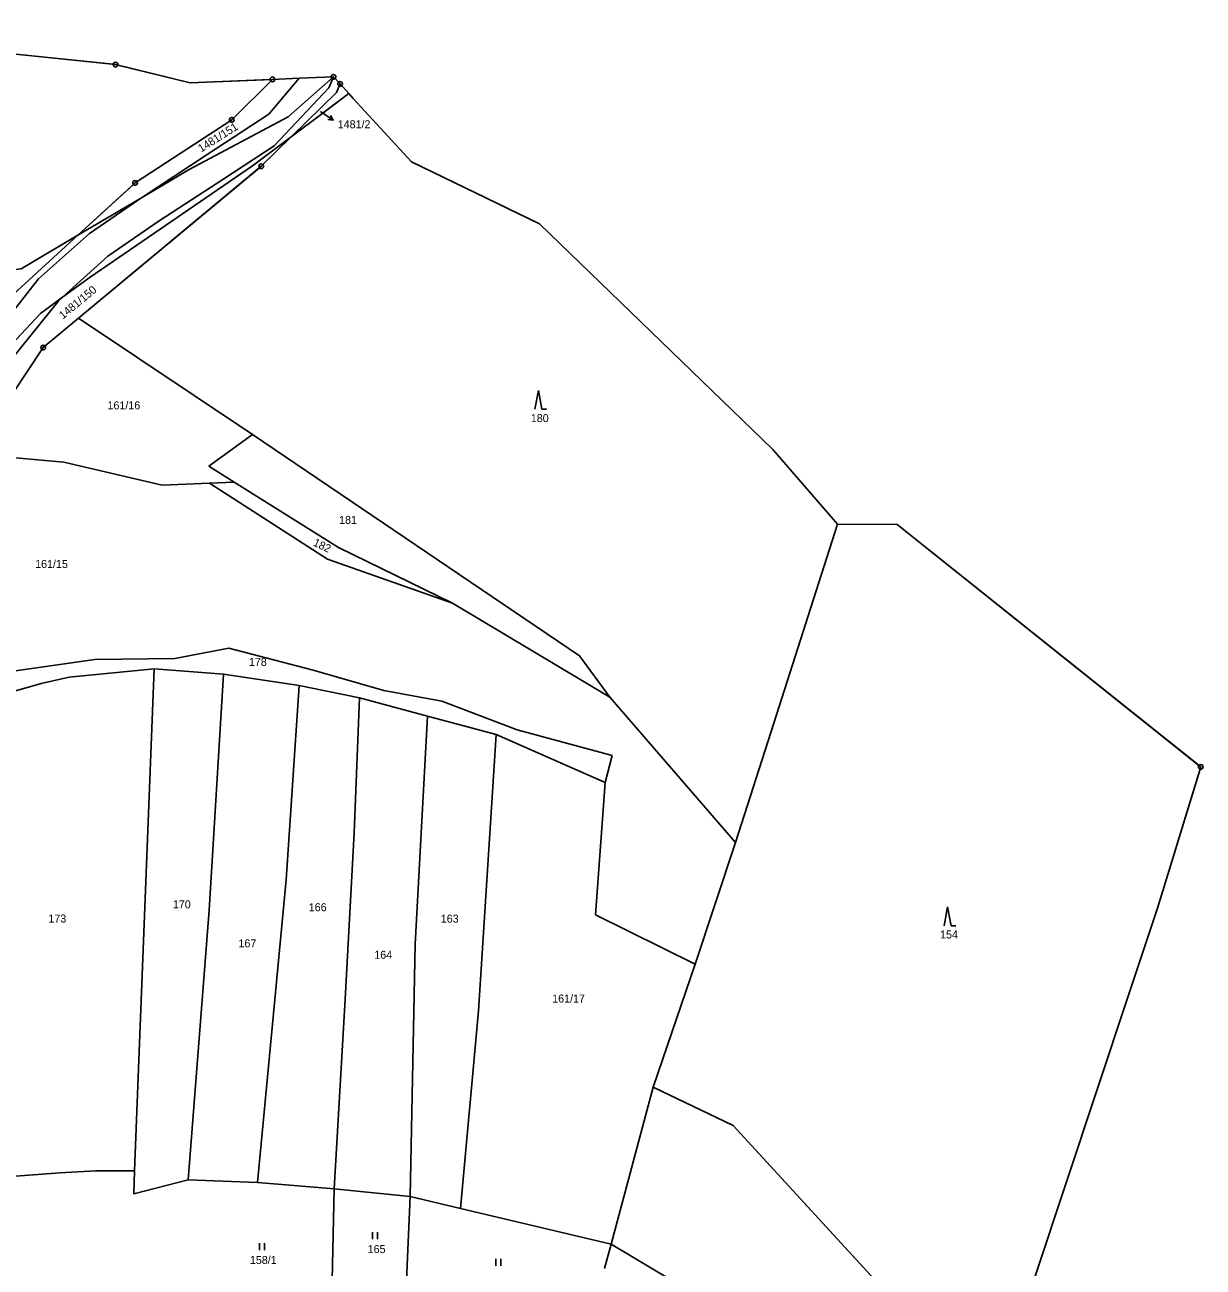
# Model space of a CAD drawing. Extents: x -760642 to -757221, y -1092371 to -1088855.
# Drawn here: x -758346.2 to -758095.9, y -1089414.4 to -1089150.5 of the extents above; entities that cross this region are included whole.
import ezdxf

# ---------------------------------------------------------------- set-up
doc = ezdxf.new("R2010")
doc.units = 0
for name, color, linetype in [('Vrstva 1', 7, 'Continuous'), ('Vrstva 13', 7, 'Continuous'), ('Vrstva 16', 7, 'Continuous'), ('Vrstva 18', 7, 'Continuous'), ('Vrstva 24', 7, 'Continuous'), ('Vrstva 25', 7, 'Continuous'), ('Vrstva 30', 7, 'Continuous'), ('Vrstva 4', 7, 'Continuous')]:
    doc.layers.add(name, color=color, linetype=linetype)

msp = doc.modelspace()

# ---------------------------------------------------------------- linework, layer by layer
at = {"layer": 'Vrstva 1'}
for p, q in [((-758302.25, -1089170.72), (-758293.6, -1089162.1)), ((-758280.62, -1089161.57), (-758290.27, -1089170.05)), ((-758280.03, -1089164.88), (-758279.25, -1089163.07)), ((-758280.03, -1089164.88), (-758289.61, -1089174.3)), ((-758289.61, -1089174.3), (-758277.37, -1089165.11)), ((-758302.25, -1089170.72), (-758322.78, -1089184.1)), ((-758290.27, -1089170.05), (-758311.27, -1089181.26)), ((-758297.83, -1089180.46), (-758289.61, -1089174.3)), ((-758289.61, -1089174.3), (-758296, -1089180.57)), ((-758296, -1089180.57), (-758334.79, -1089212.82)), ((-758297.83, -1089180.46), (-758332.36, -1089204.09)), ((-758311.27, -1089181.26), (-758321.42, -1089187.24)), ((-758322.78, -1089184.1), (-758334.92, -1089195.2)), ((-758321.42, -1089187.24), (-758334.92, -1089195.2)), ((-758334.92, -1089195.2), (-758353.94, -1089212.58)), ((-758334.92, -1089195.2), (-758347.02, -1089202.33)), ((-758332.36, -1089204.09), (-758338.21, -1089208.39)), ((-758338.21, -1089208.39), (-758342.91, -1089211.84)), ((-758342.91, -1089211.84), (-758351.13, -1089220.61)), ((-758334.79, -1089212.82), (-758342.31, -1089219.07)), ((-758297.86, -1089237.52), (-758334.79, -1089212.82)), ((-758342.31, -1089219.07), (-758357.37, -1089241.64)), ((-758297.86, -1089237.52), (-758307.12, -1089244.28)), ((-758228.38, -1089284.52), (-758297.86, -1089237.52)), ((-758357.37, -1089241.64), (-758337.94, -1089243.41)), ((-758337.94, -1089243.41), (-758317.03, -1089248.27)), ((-758307.12, -1089244.28), (-758301.74, -1089247.65)), ((-758306.95, -1089247.86), (-758301.74, -1089247.65)), ((-758301.74, -1089247.65), (-758279.56, -1089261.51)), ((-758317.03, -1089248.27), (-758306.95, -1089247.86)), ((-758281.94, -1089264.02), (-758306.95, -1089247.86)), ((-758173.59, -1089256.56), (-758187.13, -1089298.82)), ((-758279.56, -1089261.51), (-758255.35, -1089273.35)), ((-758255.35, -1089273.35), (-758281.94, -1089264.02)), ((-758255.35, -1089273.35), (-758221.9, -1089293.3)), ((-758314.36, -1089285.09), (-758302.84, -1089282.89)), ((-758302.84, -1089282.89), (-758284.96, -1089287.55)), ((-758221.9, -1089293.3), (-758228.38, -1089284.52)), ((-758355.84, -1089288.82), (-758331.34, -1089285.31)), ((-758331.34, -1089285.31), (-758314.36, -1089285.09)), ((-758342.75, -1089290.44), (-758336.79, -1089289.05)), ((-758336.79, -1089289.05), (-758318.74, -1089287.31)), ((-758322.92, -1089393.9), (-758318.74, -1089287.31)), ((-758318.74, -1089287.31), (-758303.99, -1089288.45)), ((-758303.99, -1089288.45), (-758307.04, -1089338.52)), ((-758303.99, -1089288.45), (-758287.95, -1089290.83)), ((-758284.96, -1089287.55), (-758269.97, -1089291.89)), ((-758350.4, -1089292.58), (-758342.75, -1089290.44)), ((-758287.95, -1089290.83), (-758290.7, -1089332.12)), ((-758287.95, -1089290.83), (-758275.12, -1089293.45)), ((-758269.97, -1089291.89), (-758257.63, -1089294.18)), ((-758275.12, -1089293.45), (-758276.26, -1089322.15)), ((-758275.12, -1089293.45), (-758260.65, -1089297.35)), ((-758257.63, -1089294.18), (-758241.61, -1089300.28)), ((-758195.26, -1089324.21), (-758221.9, -1089293.3)), ((-758263.32, -1089345.75), (-758260.65, -1089297.35)), ((-758260.65, -1089297.35), (-758246.05, -1089301.28)), ((-758241.61, -1089300.28), (-758221.45, -1089305.74)), ((-758187.13, -1089298.82), (-758195.26, -1089324.21)), ((-758249.83, -1089359.96), (-758246.05, -1089301.28)), ((-758246.05, -1089301.28), (-758222.9, -1089311.46)), ((-758222.9, -1089311.46), (-758221.45, -1089305.74)), ((-758222.9, -1089311.46), (-758225.01, -1089339.52)), ((-758276.26, -1089322.15), (-758278.16, -1089357.46)), ((-758195.26, -1089324.21), (-758203.78, -1089350.04)), ((-758290.7, -1089332.12), (-758296.79, -1089396.4)), ((-758307.04, -1089338.52), (-758311.53, -1089395.83)), ((-758225.01, -1089339.52), (-758203.78, -1089350.04)), ((-758264.35, -1089399.34), (-758263.32, -1089345.75)), ((-758203.78, -1089350.04), (-758212.75, -1089376.15)), ((-758278.16, -1089357.46), (-758280.49, -1089397.73)), ((-758253.63, -1089401.91), (-758249.83, -1089359.96)), ((-758212.75, -1089376.15), (-758221.64, -1089409.49)), ((-758212.75, -1089376.15), (-758195.73, -1089384.3)), ((-758195.73, -1089384.3), (-758162.53, -1089420.44)), ((-758350.93, -1089395.23), (-758338.76, -1089394.33)), ((-758338.76, -1089394.33), (-758331.15, -1089393.9)), ((-758331.15, -1089393.9), (-758322.92, -1089393.9)), ((-758323.09, -1089398.79), (-758322.92, -1089393.9)), ((-758311.53, -1089395.83), (-758323.09, -1089398.79)), ((-758311.53, -1089395.83), (-758296.79, -1089396.4)), ((-758296.79, -1089396.4), (-758280.49, -1089397.73)), ((-758280.49, -1089397.73), (-758281.08, -1089425.85)), ((-758280.49, -1089397.73), (-758264.35, -1089399.34)), ((-758265.53, -1089426.1), (-758264.35, -1089399.34)), ((-758264.35, -1089399.34), (-758253.63, -1089401.91)), ((-758253.63, -1089401.91), (-758221.64, -1089409.49)), ((-758221.64, -1089409.49), (-758223.09, -1089414.65)), ((-758182.06, -1089433.09), (-758221.64, -1089409.49))]:
    msp.add_line(p, q, dxfattribs=at)
at = {"layer": 'Vrstva 13'}
for p, q in [((-758326.93, -1089158.95), (-758349.54, -1089156.59)), ((-758311.06, -1089162.82), (-758326.93, -1089158.95)), ((-758293.6, -1089162.1), (-758311.06, -1089162.82)), ((-758287.96, -1089161.87), (-758293.6, -1089162.1)), ((-758280.62, -1089161.57), (-758287.96, -1089161.87)), ((-758279.25, -1089163.07), (-758280.62, -1089161.57)), ((-758277.37, -1089165.11), (-758279.25, -1089163.07)), ((-758276.43, -1089166.14), (-758277.37, -1089165.11)), ((-758264.05, -1089179.61), (-758276.43, -1089166.14)), ((-758236.9, -1089192.79), (-758264.05, -1089179.61)), ((-758187.32, -1089240.69), (-758236.9, -1089192.79)), ((-758173.59, -1089256.56), (-758187.32, -1089240.69)), ((-758160.89, -1089256.67), (-758173.59, -1089256.56)), ((-758096.39, -1089308.13), (-758160.89, -1089256.67)), ((-758105.01, -1089336.29), (-758096.39, -1089308.13)), ((-758105.75, -1089338.52), (-758105.01, -1089336.29)), ((-758111.82, -1089356.79), (-758105.75, -1089338.52)), ((-758131.67, -1089416.53), (-758111.82, -1089356.79))]:
    msp.add_line(p, q, dxfattribs=at)
at = {"layer": 'Vrstva 16'}
for p, q in [((-758283.42, -1089168.93), (-758283.2, -1089169.08)), ((-758283.2, -1089169.08), (-758280.735, -1089170.79))]:
    msp.add_line(p, q, dxfattribs=at)
msp.add_lwpolyline([(-758281.272, -1089169.81), (-758280.735, -1089170.79), (-758281.842, -1089170.631)], dxfattribs=at)
at = {"layer": 'Vrstva 24'}
for centre, radius in [((-758326.93, -1089158.95), 0.5), ((-758326.93, -1089158.95), 0.5), ((-758326.93, -1089158.95), 0.0327), ((-758326.93, -1089158.95), 0.0327), ((-758293.6, -1089162.1), 0.5), ((-758293.6, -1089162.1), 0.0327), ((-758280.62, -1089161.57), 0.5), ((-758280.62, -1089161.57), 0.0327), ((-758279.25, -1089163.07), 0.5), ((-758279.25, -1089163.07), 0.0327), ((-758302.25, -1089170.72), 0.5), ((-758302.25, -1089170.72), 0.0327), ((-758296, -1089180.57), 0.5), ((-758296, -1089180.57), 0.0327), ((-758322.78, -1089184.1), 0.5), ((-758322.78, -1089184.1), 0.0327), ((-758342.31, -1089219.07), 0.5), ((-758342.31, -1089219.07), 0.0327), ((-758096.39, -1089308.13), 0.5), ((-758096.39, -1089308.13), 0.0327)]:
    msp.add_circle(centre, radius, dxfattribs=at)
at = {"layer": 'Vrstva 25'}
for p, q in [((-758237.112, -1089228.179), (-758237.845, -1089232.179)), ((-758237.112, -1089228.179), (-758236.379, -1089232.179)), ((-758236.379, -1089232.179), (-758235.379, -1089232.179)), ((-758150.182, -1089337.859), (-758150.915, -1089341.859)), ((-758150.182, -1089337.859), (-758149.449, -1089341.859)), ((-758149.449, -1089341.859), (-758148.449, -1089341.859)), ((-758272.337, -1089406.945), (-758272.337, -1089408.445)), ((-758271.315, -1089408.445), (-758271.315, -1089406.945)), ((-758296.337, -1089409.265), (-758296.337, -1089410.765)), ((-758295.315, -1089410.765), (-758295.315, -1089409.265)), ((-758246.137, -1089412.595), (-758246.137, -1089414.095)), ((-758245.115, -1089414.095), (-758245.115, -1089412.595))]:
    msp.add_line(p, q, dxfattribs=at)
at = {"layer": 'Vrstva 30'}
for points in [[(-758327.427, -1089158.898), (-758349.54, -1089156.59), (-758372.936, -1089150.525)], [(-758294.1, -1089162.121), (-758311.06, -1089162.82), (-758326.444, -1089159.068)], [(-758592.01, -1089161.543), (-758568.43, -1089249.17), (-758567.51, -1089252.75), (-758555.5, -1089246.63), (-758548.71, -1089234.2), (-758548.97, -1089223.27), (-758549.63, -1089200.95), (-758518.67, -1089199.48), (-758482.93, -1089197.19), (-758451.29, -1089201.78), (-758450.36, -1089199.52), (-758448.76, -1089195.17), (-758390.33, -1089207.55), (-758347.02, -1089202.33), (-758334.92, -1089195.2), (-758323.149, -1089184.437)], [(-758301.896, -1089170.367), (-758293.954, -1089162.453)], [(-758296.384, -1089180.89), (-758334.79, -1089212.82), (-758297.86, -1089237.52), (-758228.38, -1089284.52), (-758221.9, -1089293.3), (-758195.26, -1089324.21), (-758187.13, -1089298.82), (-758173.59, -1089256.56), (-758187.32, -1089240.69), (-758236.9, -1089192.79), (-758264.05, -1089179.61), (-758276.43, -1089166.14), (-758277.37, -1089165.11), (-758282.918, -1089169.276), (-758289.61, -1089174.3), (-758295.643, -1089180.22)], [(-758322.361, -1089183.827), (-758302.669, -1089170.993)], [(-758096.781, -1089307.818), (-758160.89, -1089256.67), (-758173.59, -1089256.56), (-758187.13, -1089298.82), (-758195.26, -1089324.21), (-758203.78, -1089350.04), (-758212.75, -1089376.15), (-758195.73, -1089384.3), (-758162.53, -1089420.44), (-758137.95, -1089436.07), (-758131.823, -1089417.006)], [(-758131.512, -1089416.056), (-758111.82, -1089356.79), (-758105.75, -1089338.52), (-758105.01, -1089336.29), (-758096.536, -1089308.608)]]:
    msp.add_lwpolyline(points, dxfattribs=at)
for centre, start, end in [((-758326.93, -1089158.95), 174.04113, 180), ((-758326.93, -1089158.95), 180, 346.29553), ((-758293.6, -1089162.1), 182.36137, 224.90047), ((-758302.25, -1089170.72), 44.90047, 180), ((-758302.25, -1089170.72), 180, 213.09346), ((-758296, -1089180.57), 219.74013, 0), ((-758296, -1089180.57), 0, 44.45693), ((-758322.78, -1089184.1), 33.09346, 180), ((-758322.78, -1089184.1), 180, 222.4377), ((-758096.39, -1089308.13), 141.4161, 180), ((-758096.39, -1089308.13), 180, 252.98023)]:
    msp.add_arc(centre, 0.5, start, end, dxfattribs=at)
at = {"layer": 'Vrstva 4'}
for p, q in [((-758294.38, -1089169.52), (-758287.96, -1089161.87)), ((-758280.62, -1089161.57), (-758281.6, -1089163.9)), ((-758281.6, -1089163.9), (-758293.23, -1089176.22)), ((-758307.46, -1089178.04), (-758294.38, -1089169.52)), ((-758293.23, -1089176.22), (-758303.92, -1089183.24)), ((-758321.42, -1089187.24), (-758307.46, -1089178.04)), ((-758303.92, -1089183.24), (-758317.7, -1089192.17)), ((-758332.44, -1089194.87), (-758322.28, -1089187.81)), ((-758321.42, -1089187.24), (-758322.28, -1089187.81)), ((-758317.7, -1089192.17), (-758328.58, -1089199.66)), ((-758343.28, -1089204.5), (-758332.44, -1089194.87)), ((-758328.58, -1089199.66), (-758338.21, -1089208.39)), ((-758355.44, -1089219.87), (-758343.28, -1089204.5)), ((-758338.92, -1089209.03), (-758350.99, -1089223.97)), ((-758338.21, -1089208.39), (-758338.92, -1089209.03))]:
    msp.add_line(p, q, dxfattribs=at)

# ---------------------------------------------------------------- texts
at = {"layer": 'Vrstva 16'}
msp.add_text('1481/2', height=1.7, dxfattribs=at).set_placement((-758279.74, -1089172.49))
at = {"layer": 'Vrstva 18'}
for s, height, p in [('1481/2', 0.1, (-758283.565, -1089168.93)), ('161/16', 1.7, (-758328.65, -1089232.19)), ('180', 1.7, (-758238.72, -1089234.89)), ('181', 1.7, (-758279.45, -1089256.51)), ('161/15', 1.7, (-758344.02, -1089265.88)), ('178', 1.7, (-758298.61, -1089286.68)), ('170', 1.7, (-758314.76, -1089338.17)), ('166', 1.7, (-758285.9, -1089338.78)), ('173', 1.7, (-758341.2, -1089341.18)), ('163', 1.7, (-758257.85, -1089341.21)), ('167', 1.7, (-758300.83, -1089346.45)), ('154', 1.7, (-758151.778, -1089344.57)), ('164', 1.7, (-758271.97, -1089348.88)), ('161/17', 1.7, (-758234.18, -1089358.17)), ('165', 1.7, (-758273.38, -1089411.38)), ('158/1', 1.7, (-758298.4, -1089413.7))]:
    msp.add_text(s, height=height, dxfattribs=at).set_placement(p)
for s, rotation, p in [('1481/151', 32.29767, (-758308.76, -1089177.68)), ('1481/150', 39.58299, (-758338.11, -1089213.13)), ('182', 334.52712, (-758285.12, -1089261.06))]:
    msp.add_text(s, height=1.7, rotation=rotation, dxfattribs=at).set_placement(p)

doc.saveas('drawing.dxf')
